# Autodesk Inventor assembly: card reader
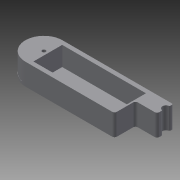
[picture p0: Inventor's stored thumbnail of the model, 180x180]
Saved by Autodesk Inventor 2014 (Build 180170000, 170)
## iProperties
Created: 2015-01
Part Number: card reader
Document SubType Name: Assembly
Designer: Drano
Author: Drano
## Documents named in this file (3)
- C:\Users\Drano\Documents\SD swiss army\card reader.iam
- C:\Users\Drano\Documents\SD swiss army\backplate.ipt
- C:\Users\Drano\Documents\SD swiss army\card reader.ipt
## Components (2 placed, 2 different names)
1. backplate:1 — Mate:1, Mate:2, Flush:1
2. card reader:1 — Mate:1, Mate:2, Flush:1
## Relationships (3: Mate 2, Flush 1)
- Mate:1: backplate:1 ↔ card reader:1
- Mate:2: backplate:1 ↔ card reader:1
- Flush:1: backplate:1 ↔ card reader:1
